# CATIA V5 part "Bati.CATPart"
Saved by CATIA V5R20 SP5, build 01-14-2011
Part number: Bati
Publications: "Longueur_rainure"
Bounding box of the stored display mesh (mm): x -10 to 15, y -20 to 20, z -30 to 110
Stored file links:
  D:\Dropbox\IAO_2011\MMS_GR3\IAO_2011_1475_rguinot\IAO\IAO_2011_1475_rguinot\Bati.CATPart
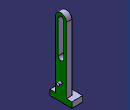
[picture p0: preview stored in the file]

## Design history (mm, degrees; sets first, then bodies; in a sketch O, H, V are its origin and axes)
Parameters
  Longueur_rainure = 60 mm
Body1 (main body)
  Sketch1 on yz-plane, origin (0, 0, 0), H (0, 1, 0), V (0, 0, 1)
    line L1 (-10, -20) -> (-10, 100)
    arc A1 centre (0, 100) radius 10 from (-10, 100) to (10, 100) cw
    point P3 (0, 100)
    line L2 (10, 100) -> (10, -20)
    line L3 (10, -20) -> (-10, -20)
    line L4 (-5, 100) -> (-5, 40)
    arc A2 centre (0, 40) radius 5 from (-5, 40) to (5, 40) ccw
    point P8 (0, 40)
    line L5 (5, 40) -> (5, 100)
    arc A3 centre (0, 100) radius 5 from (5, 100) to (-5, 100) ccw
    point P11 (0, 100)
    reference intersected line E1 through (0, 0) direction (0, 1) from zx-plane
    radius A3 = 5
    radius A1 = 10
    length L3 = 20
    distance O L3 = 20
    length L5 = 60 {= Longueur_rainure}
    distance P8 O = 40
    vertical: L1 V, L4 V
    tangency: A1 L1, L2 A1, A2 L4, L5 A2, A3 L4, A3 L5
    horizontal: L3 H
    coincidence: P11 P3
    symmetry: L5 L4 E1
  Pad1: profile Sketch1, direction (1, 0, 0), length 10
  Sketch2 on face of Pad1 from Sketch1.L3, origin (0, 0, -20), H (1, 0, 0), V (0, -1, 0)
    line L1 (-10, 20) -> (10, 20)
    line L2 (10, 20) -> (10, -20)
    line L3 (10, -20) -> (-10, -20)
    line L4 (-10, -20) -> (-10, 20)
    reference projected line E1 (10, 10) -> (10, -10) from edge [face of Pad1 from Sketch1.L3 | end face of Pad1]
    reference projected line E2 (0, 10) -> (0, -10) from edge [start face of Pad1 | face of Pad1 from Sketch1.L3]
    reference projected line E3 (0, 10) -> (10, 10) from edge [face of Pad1 from Sketch1.L3 | face of Pad1 from Sketch1.L1]
    reference projected line E4 (0, -10) -> (10, -10) from edge [face of Pad1 from Sketch1.L2 | face of Pad1 from Sketch1.L3]
    distance L2 E1 = 0
    distance L4 E2 = 10
    distance E3 L1 = 10
    distance L3 E4 = 10
    horizontal: L1 H, L3 H
    vertical: L2 V, L4 V
  Pad2: profile Sketch2, direction (0, 0, -1), length 10
  Sketch3 on end face of Pad1, origin (10, 0, 0), H (0, 1, 0), V (0, 0, 1)
    circle A1 centre (0, 0) radius 2.5
    radius A1 = 2.5
  Pad3: profile Sketch3, direction (1, 0, 0), length 5
  Sketch4 on end face of Pad3, origin (15, 0, 0), H (0, 1, 0), V (0, 0, 1)
    axis line L1 (94, 0) -> (-166, 0)
    point P1 (94, 0)
    coincidence: P1 H
    horizontal: L1 H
